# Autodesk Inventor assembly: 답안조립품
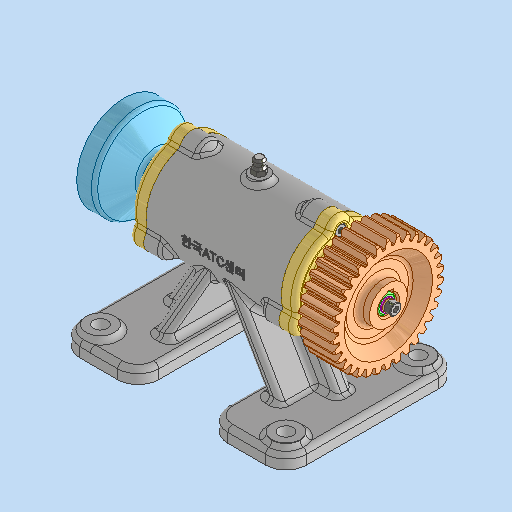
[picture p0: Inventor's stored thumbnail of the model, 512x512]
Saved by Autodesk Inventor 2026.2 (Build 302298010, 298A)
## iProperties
Created: 2026-04
Part Number: 답안조립품
Document SubType Name: Assembly
Designer: PC-2-03
Author: PC-2-03
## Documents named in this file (16)
- C:\Users\PC-2-03\Desktop\760403V1007\답안조립품.iam
- C:\Users\PC-2-03\Desktop\760403V1007\본체.ipt
- C:\Users\PC-2-03\Desktop\760403V1007\축.ipt
- C:\Users\PC-2-03\Desktop\760403V1007\커버.ipt
- C:\Users\PC-2-03\Desktop\760403V1007\오일 실 20 35 8.ipt
- C:\Users\PC-2-03\Desktop\760403V1007\깊은 홈 볼 베어링 6004.ipt
- C:\Users\PC-2-03\Desktop\760403V1007\스퍼 기어.ipt
- C:\Users\PC-2-03\Desktop\760403V1007\평행 키 4x4x14.ipt
- C:\Users\PC-2-03\Desktop\760403V1007\평 와셔 M4.ipt
- C:\Users\PC-2-03\Desktop\760403V1007\스프링 와셔 M4.ipt
- C:\Users\PC-2-03\Desktop\760403V1007\플러그 M6x0,75.ipt
- C:\Users\PC-2-03\Desktop\760403V1007\6각 구멍붙이 볼트 M4x12.ipt
- C:\Users\PC-2-03\Desktop\760403V1007\플랜지.ipt
- C:\Users\PC-2-03\Desktop\760403V1007\엔드 캡.ipt
- C:\Users\PC-2-03\Desktop\760403V1007\그리스 니플 M6x0,75.ipt
- C:\Users\PC-2-03\Desktop\760403V1007\실링.ipt
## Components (11 placed, 4 different names)
1. 6각 구멍붙이 볼트 M4x12:1
2. 플랜지:1
3. 6각 구멍붙이 볼트 M4x12:2
4. 그리스 니플 M6x0,75:1
5. 플러그 M6x0,75:1
6. 6각 구멍붙이 볼트 M4x12:3
7. 6각 구멍붙이 볼트 M4x12:5
8. 6각 구멍붙이 볼트 M4x12:6
9. 6각 구멍붙이 볼트 M4x12:4
10. 6각 구멍붙이 볼트 M4x12:7
11. 6각 구멍붙이 볼트 M4x12:8
